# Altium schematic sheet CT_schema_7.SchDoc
size 256 x 245 mm
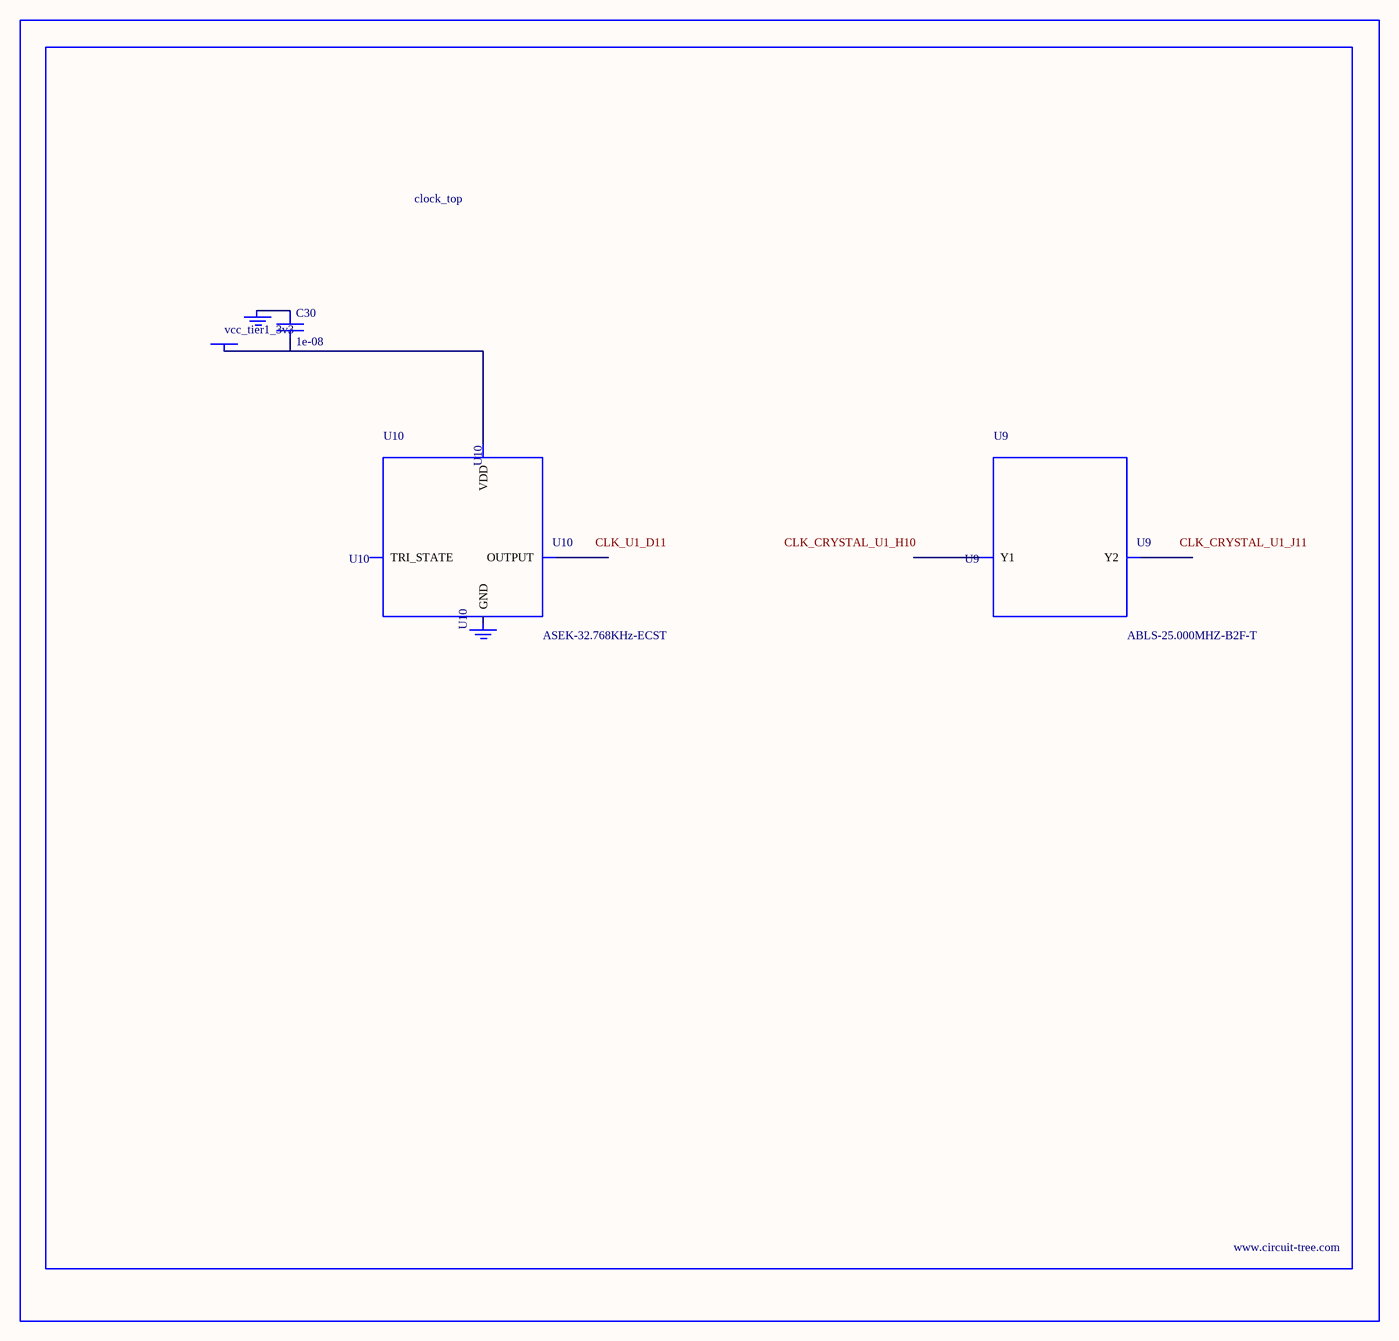
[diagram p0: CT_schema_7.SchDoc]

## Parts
BORDER6  (no value)
C30  1e-08  [C0402]
GND_INSTANCE_6_0  (no value)
GND_INSTANCE_6_1  (no value)
POWER_INSTANCE_6_0  vcc_tier1_3v3
U9  ABLS-25.000MHZ-B2F-T  [ABLS-25.000MHZ-B2F-T]
U10  ASEK-32.768KHz-ECST  [ASEK]

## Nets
NetC30_1: C30.1 GND_INSTANCE_6_0.0(GND)
NetC30_2: C30.2 POWER_INSTANCE_6_0.0(PWR) U10.4(VDD)

Not connected (* = marked no-connect by the designer): GND_INSTANCE_6_1 0(GND); U9 1(Y1) 2(Y2); U10 1(TRI_STATE) 2(GND) 3(OUTPUT)

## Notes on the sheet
- Labels drawn without touching a wire or pin: CLK_CRYSTAL_U1_H10, CLK_CRYSTAL_U1_J11, CLK_U1_D11

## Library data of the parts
BORDER6 = BORDER_PAGE6
C30 = C0402C103K3RAC
GND_INSTANCE_6_0 GND_INSTANCE_6_1 = GND
POWER_INSTANCE_6_0 = PWR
